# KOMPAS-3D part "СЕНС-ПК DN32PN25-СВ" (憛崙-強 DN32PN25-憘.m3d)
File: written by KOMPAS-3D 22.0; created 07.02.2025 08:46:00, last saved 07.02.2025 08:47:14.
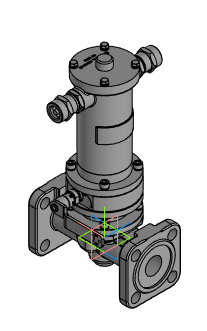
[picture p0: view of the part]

Document properties: Автор: setup; Полное имя файла: \\10.10.77.77\!! users\Савин А.Г\!Клапаны 3D для заказчика\СЕНС-ПК\1. СЕНС-ПК\СЕНС-ПК DN32PN25-СВ.m3d

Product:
- Body: Тело 1
    Масса: 11.446992
- Part/product: СЕНС-ПК DN32PN25-СВ
    Масса: 11.326737

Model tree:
1. Операция без истории:1
2. Эскиз:1  (with: Операция без истории:1)
3. Элемент выдавливания:1
     Расстояние 1 = 14
4. Фаска:1  (with: Элемент выдавливания:1)
     Угол = 45; Длина 1 = 2; Длина 2 = 2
